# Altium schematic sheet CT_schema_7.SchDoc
size 386 x 278 mm
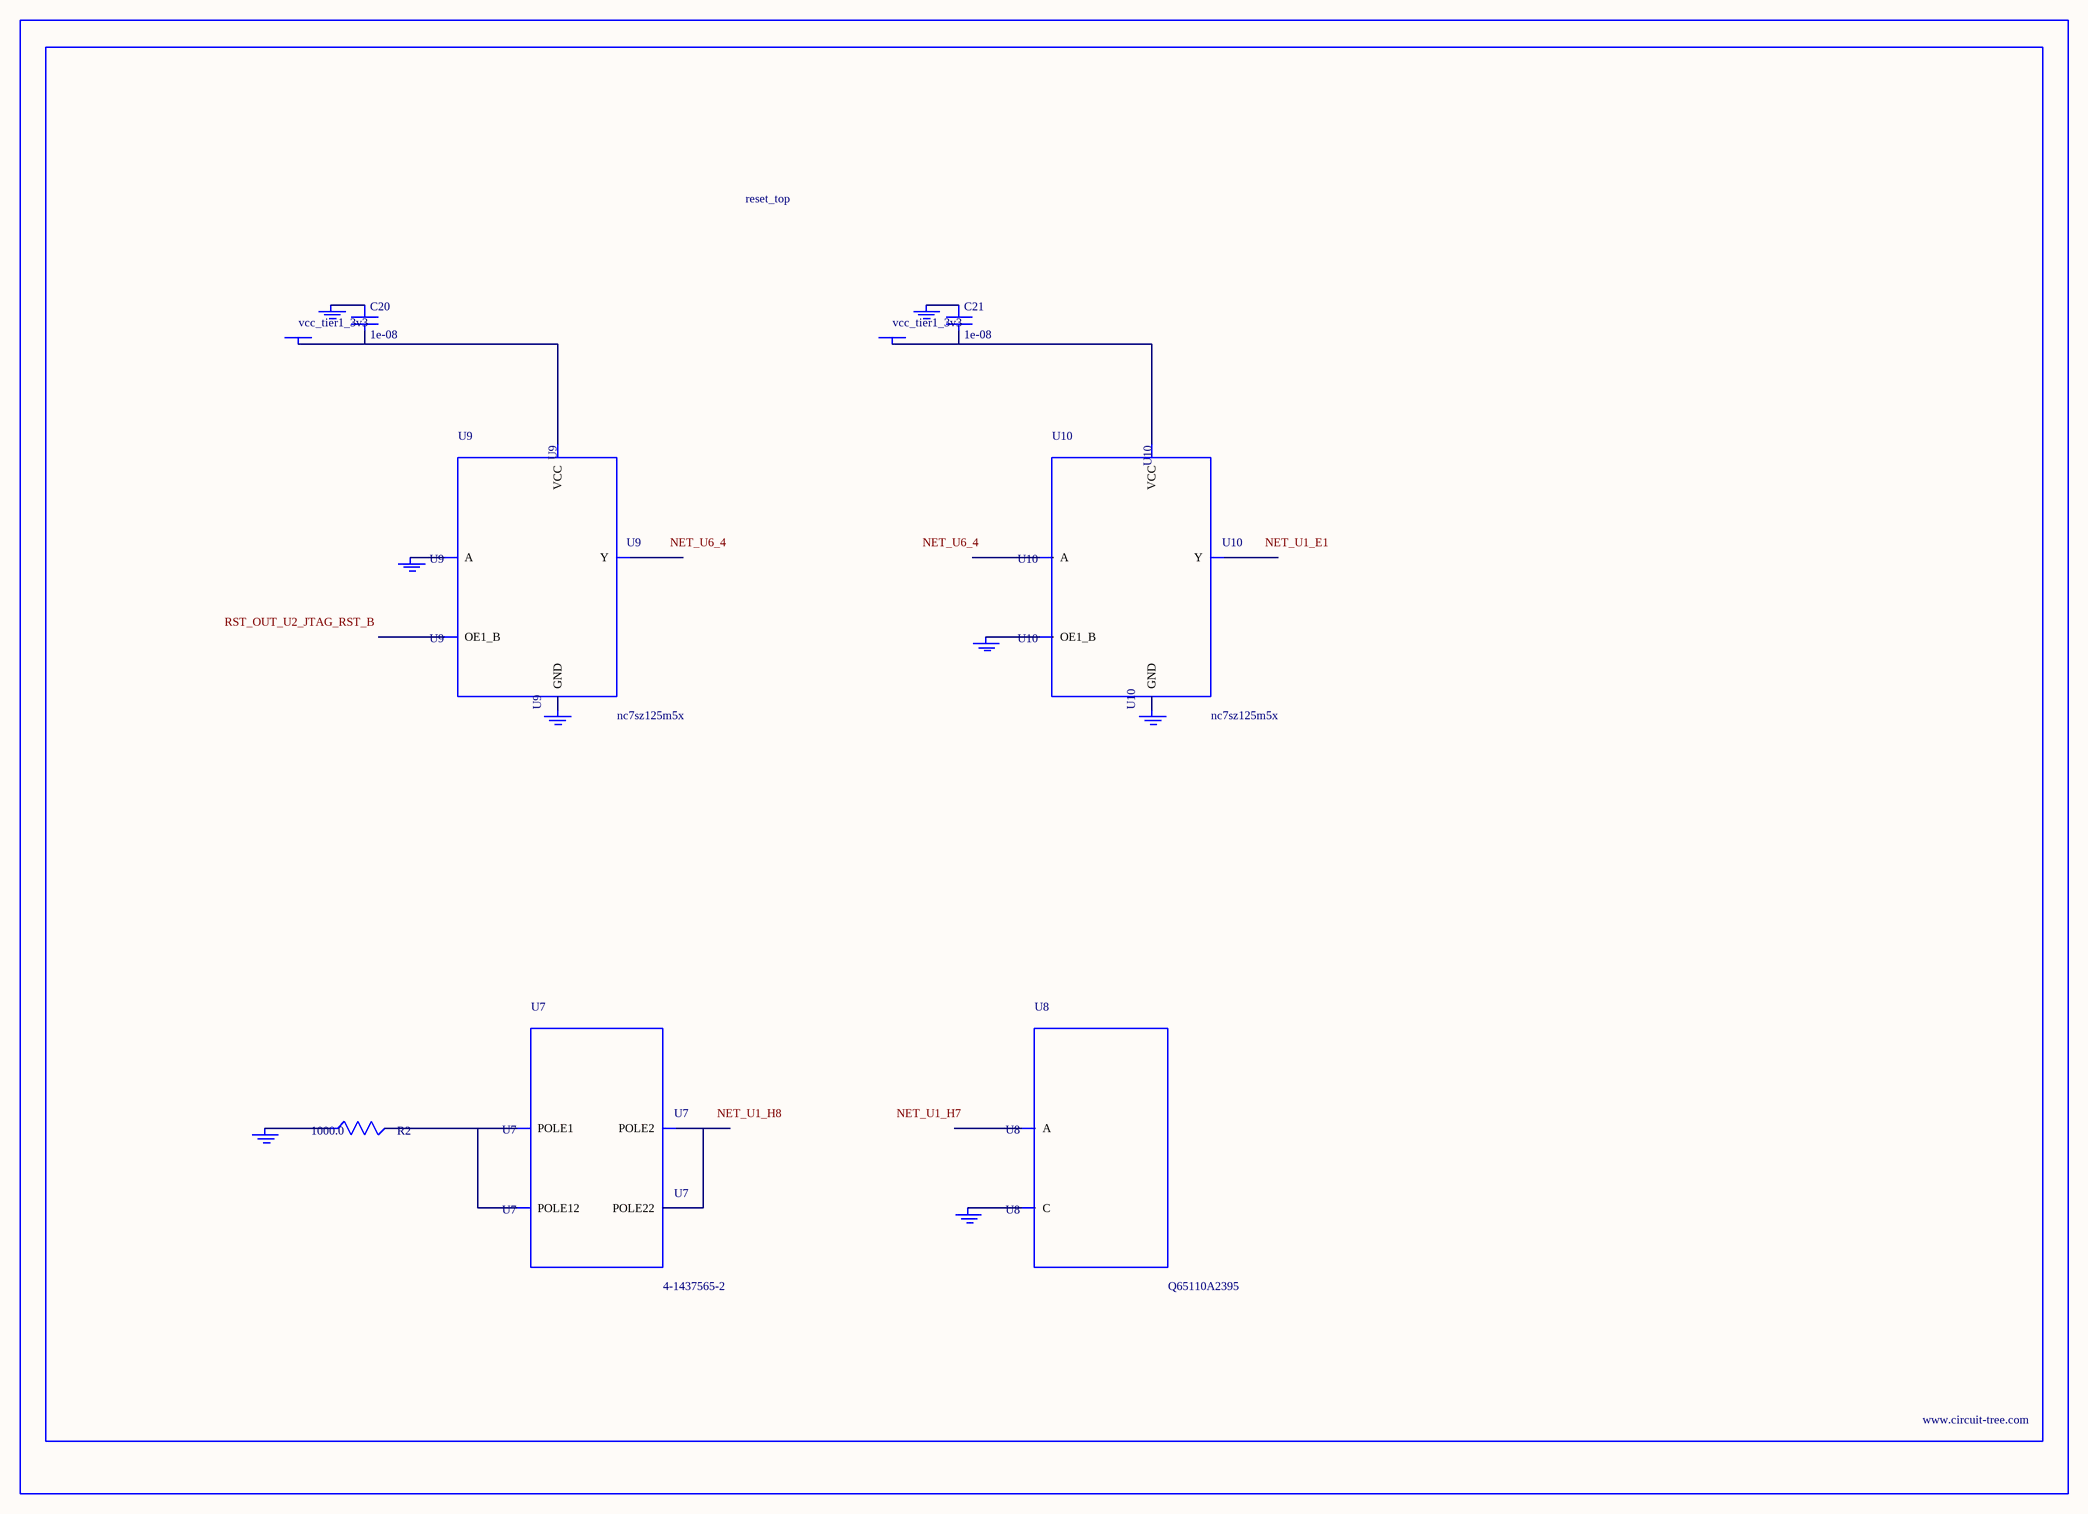
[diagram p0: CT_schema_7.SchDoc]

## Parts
BORDER6  (no value)
C20  1e-08  [C0402]
C21  1e-08  [C0402]
GND_INSTANCE_6_0  (no value)
GND_INSTANCE_6_1  (no value)
GND_INSTANCE_6_2  (no value)
GND_INSTANCE_6_3  (no value)
GND_INSTANCE_6_4  (no value)
GND_INSTANCE_6_5  (no value)
GND_INSTANCE_6_6  (no value)
GND_INSTANCE_6_7  (no value)
POWER_INSTANCE_6_0  vcc_tier1_3v3
POWER_INSTANCE_6_1  vcc_tier1_3v3
R2  1000.0  [R0603]
U7  4-1437565-2  [SW_4-1437565-2]
U8  Q65110A2395  [LGM67K-G1J2-24-Z]
U9  nc7sz125m5x  [NC7SZ125M5X]
U10  nc7sz125m5x  [NC7SZ125M5X]

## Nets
NetC20_1: C20.1 GND_INSTANCE_6_2.0(GND)
NetC20_2: C20.2 POWER_INSTANCE_6_0.0(PWR) U9.5(VCC)
NetC21_1: C21.1 GND_INSTANCE_6_5.0(GND)
NetC21_2: C21.2 POWER_INSTANCE_6_1.0(PWR) U10.5(VCC)
NetGND_INSTANCE_6_0_0: GND_INSTANCE_6_0.0(GND) R2.1
NetGND_INSTANCE_6_1_0: GND_INSTANCE_6_1.0(GND) U8.C
NetGND_INSTANCE_6_3_0: GND_INSTANCE_6_3.0(GND) U9.2(A)
NetGND_INSTANCE_6_4_0: GND_INSTANCE_6_4.0(GND) U9.3(GND)
NetGND_INSTANCE_6_6_0: GND_INSTANCE_6_6.0(GND) U10.1(OE1_B)
NetGND_INSTANCE_6_7_0: GND_INSTANCE_6_7.0(GND) U10.3(GND)
NetR2_2: R2.2 U7.1(POLE1) U7.2(POLE12)
NetU7_3: U7.3(POLE2) U7.4(POLE22)

Not connected (* = marked no-connect by the designer): U8 A; U9 1(OE1_B) 4(Y); U10 2(A) 4(Y)

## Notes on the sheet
- Labels drawn without touching a wire or pin: NET_U1_E1, NET_U1_H7, NET_U1_H8, NET_U6_4, RST_OUT_U2_JTAG_RST_B

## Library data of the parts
BORDER6 = BORDER_PAGE6
C20 C21 = C0402C103K3RAC
GND_INSTANCE_6_0-GND_INSTANCE_6_7 = GND
POWER_INSTANCE_6_0 POWER_INSTANCE_6_1 = PWR
R2 = RC0603JR-071KL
